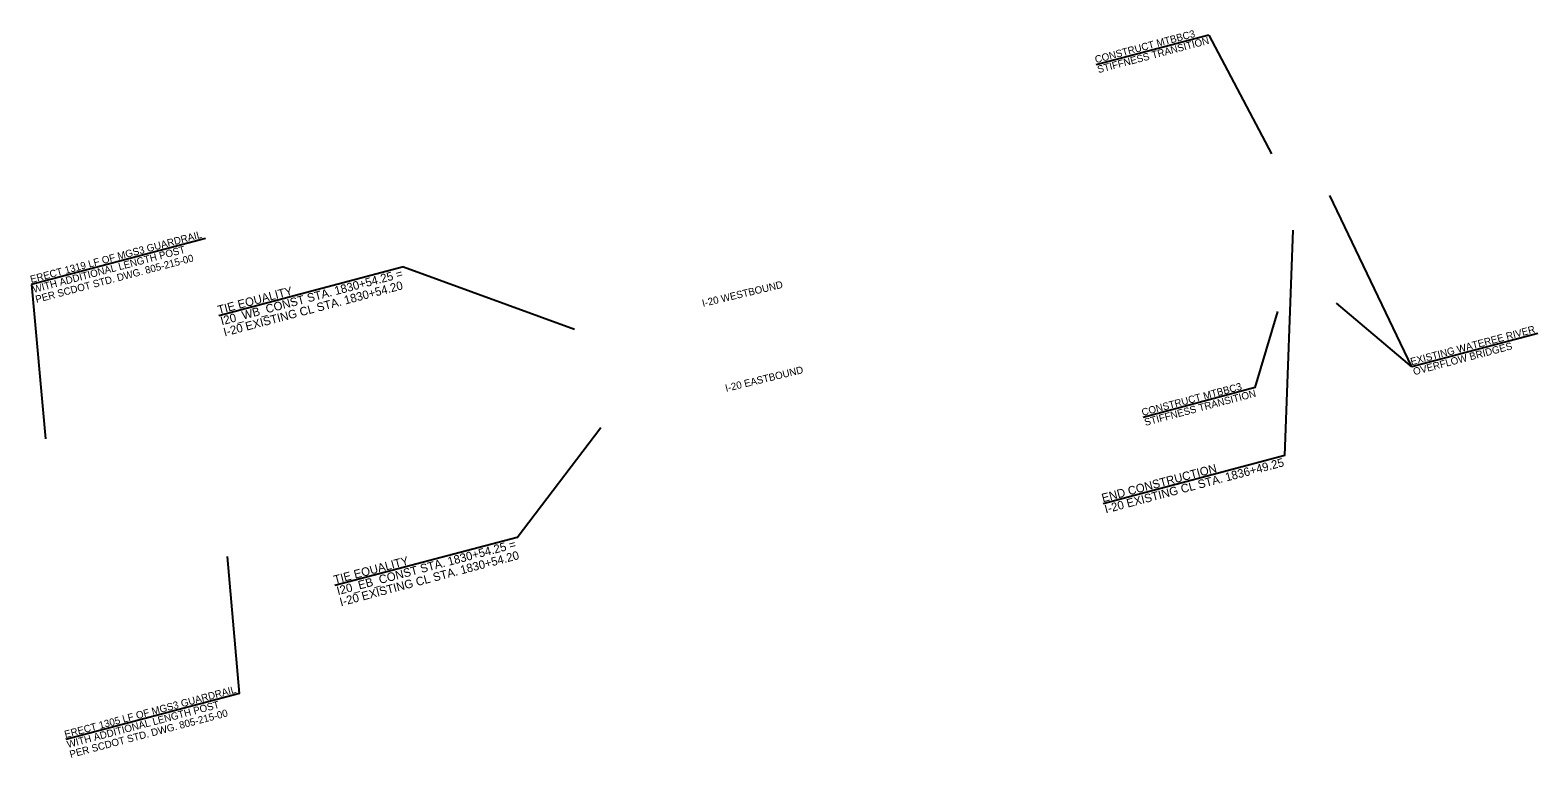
# Model space of a CAD drawing. Extents: x 2110155 to 2114862, y 866944 to 868497.
# Drawn here: x 2113618 to 2114862, y 867897 to 868497 of the extents above; entities that cross this region are included whole.
import ezdxf

# ---------------------------------------------------------------- set-up
doc = ezdxf.new("R2010")
doc.units = 0
doc.layers.add('RD_SHT_Bndy', color=7, linetype='Continuous')

msp = doc.modelspace()

# ---------------------------------------------------------------- linework, layer by layer
at = {"layer": 'RD_SHT_Bndy'}
for p, q in [((2114590.2, 868493.2), (2114497.2, 868468.6)), ((2113762.3, 868325.4), (2113618.9, 868287.4)), ((2113925.7, 868302), (2113773.4, 868261.6)), ((2114757.8, 868219.5), (2114695.6, 868272.1)), ((2114861.8, 868247), (2114757.8, 868219.5)), ((2114628.6, 868202.3), (2114536, 868177.7)), ((2114652.9, 868146.2), (2114503.1, 868106.5)), ((2114019.4, 868078.8), (2113869.2, 868039)), ((2113790.5, 867950), (2113647.1, 867912))]:
    msp.add_line(p, q, dxfattribs=at)
for points in [[(2114590.2, 868493.2), (2114642, 868395.1)], [(2114757.8, 868219.5), (2114690, 868360.9)], [(2114652.9, 868146.2), (2114659.8, 868332.3)], [(2113925.7, 868302), (2114066.9, 868250.6)], [(2113618.9, 868287.4), (2113630.2, 868160.2)], [(2114628.6, 868202.3), (2114647.3, 868265.1)], [(2114019.4, 868078.8), (2114088.5, 868169.4)], [(2113790.5, 867950), (2113780.4, 868063.1)]]:
    msp.add_lwpolyline(points, dxfattribs=at)

# ---------------------------------------------------------------- texts
for s, height, rotation, p in [('CONSTRUCT MTBBC3', 6, 14.8448, (2114497.1, 868469.9)), ('STIFFNESS TRANSITION', 6, 14.8448, (2114499.2, 868461.7)), ('ERECT 1319 LF OF MGS3 GUARDRAIL', 6, 14.8448, (2113618.6, 868288.6)), ('WITH ADDITIONAL LENGTH POST', 6, 14.8448, (2113620.7, 868280.4)), ('PER SCDOT STD. DWG. 805-215-00', 6, 14.8448, (2113622.9, 868272.1)), ('I20_WB_CONST STA. 1830+54.25 =', 7, 14.8448, (2113775.8, 868253.7)), ('I-20 EXISTING CL STA. 1830+54.20', 7, 14.8448, (2113778.2, 868244.5)), ('I-20 WESTBOUND', 6, 13.4386, (2114172.9, 868268.9)), ('TIE EQUALITY', 7, 14.8448, (2113773.4, 868262.9)), ('EXISTING WATEREE RIVER', 6, 14.8448, (2114757.5, 868220.7)), ('OVERFLOW BRIDGES', 6, 14.8448, (2114759.7, 868212.5)), ('I-20 EASTBOUND', 6, 13.7086, (2114192, 868198.8)), ('CONSTRUCT MTBBC3', 6, 14.8448, (2114535.7, 868178.9)), ('STIFFNESS TRANSITION', 6, 14.8448, (2114537.9, 868170.7)), ('END CONSTRUCTION', 7, 14.8448, (2114502.9, 868107.7)), ('I-20 EXISTING CL STA. 1836+49.25', 7, 14.8448, (2114505.3, 868098.5)), ('I20_EB_CONST STA. 1830+54.25 =', 7, 14.8448, (2113871.7, 868031.1)), ('I-20 EXISTING CL STA. 1830+54.20', 7, 14.8448, (2113874.1, 868021.9)), ('TIE EQUALITY', 7, 14.8448, (2113869.2, 868040.3)), ('ERECT 1305 LF OF MGS3 GUARDRAIL', 6, 14.8448, (2113646.8, 867913.2)), ('WITH ADDITIONAL LENGTH POST', 6, 14.8448, (2113648.9, 867905)), ('PER SCDOT STD. DWG. 805-215-00', 6, 14.8448, (2113651.1, 867896.8))]:
    msp.add_text(s, height=height, rotation=rotation, dxfattribs=at).set_placement(p)

doc.saveas('drawing.dxf')
